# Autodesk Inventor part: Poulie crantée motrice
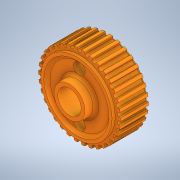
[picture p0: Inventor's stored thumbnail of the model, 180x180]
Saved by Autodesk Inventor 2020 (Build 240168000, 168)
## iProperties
Created: 2003-05
Part Number: Poulie crantée motrice
Material: Générique
Document SubType Name: Modeling
Designer: Bruno
Density: 1 g/cm^3
Appearance: Par défaut
Author: Bruno
Sending System: SolidWorks 2011
Last Author: frederic
Last Saved: 2012-02-20
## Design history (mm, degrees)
feature "Enlèv. mat.-Extru.3"
node "Solide1"
